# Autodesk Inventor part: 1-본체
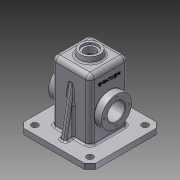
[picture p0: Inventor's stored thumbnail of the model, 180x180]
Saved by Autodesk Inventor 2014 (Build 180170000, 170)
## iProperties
Created: 2016-02
Part Number: 1-본체
Material: 알루미늄 6061
Document SubType Name: Modeling
Designer: G.C.Oh
Density: 2.71 g/cm^3
Appearance: 알루미늄 - 평지
Mass: 932.812 g
Surface Area: 1043.49 cm^2
Volume: 344.211 cm^3
Author: G.C.Oh
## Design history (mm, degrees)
sketch "스케치1"
  geometry: L1 (65, -65)-(-65, -65); L2 (-65, -65)-(-65, 65); L3 (-65, 65)-(65, 65); L4 (65, 65)-(65, -65); L5 (65, -65)-(-65, 65); L6 (-65, -65)-(65, 65); 1 further point
  constraints: 12 end point, 2 midpoint, 2 parallel, 1 horizontal, 1 perpendicular
  dimensions: "d0" = 130 distance of L2.end L3.end; "d1" = 130 distance of L1.end L2.end
extrude "돌출1" new body sketch "스케치1" distance "d2" = 10; taper "d3" = 0 deg
sketch "스케치2"
  geometry: L1 (-35, -35)-(35, -35); L2 (35, -35)-(35, 35); L3 (35, 35)-(-35, 35); L4 (-35, 35)-(-35, -35); L5 (-35, -35)-(35, 35); L6 (35, -35)-(-35, 35); 1 further point
  constraints: 12 end point, 2 midpoint, 2 parallel, 1 horizontal, 1 perpendicular
  dimensions: "d4" = 70 distance of L1.end L2.end; "d5" = 70 distance of L2.end L3.end
extrude "돌출2" join sketch "스케치2" distance "d6" = 110; taper "d7" = 0 deg
sketch "스케치3"
  geometry: L1 (0, 120)-(-20, 120); L2 (-20, 120)-(-18.237, 130); L3 (-18.237, 130)-(0, 130); L4 (0, 130)-(0, 120); L5 (-35, 10)-(-35, 120) reference; L6 (-35, 120)-(35, 120) reference; 1 further point
  constraints: 8 end point, 1 collinear, 1 horizontal, 1 parallel, 1 perpendicular, 1 vertical alignment
  dimensions: "d9" = 40 diameter of L1.end L4; "d10" = 10 deg angle of L5 L2; "d11" = 10 distance between parallel lines of L1 L3
revolve "회전1" sketch "스케치3" stored, may be unused: angle "d12" = 90 deg
fillet "모깎기1" dims "d13" = 8
sketch "스케치4"
  geometry: C1 r 27.5 at (0, 55); 1 further point
  constraints: 1 centre point, 1 vertical alignment
  dimensions: "d14" = 55 distance of point (0, 0) C1.centre; "d15" = 55 diameter of C1
extrude "돌출3" join sketch "스케치4" stored distance "d16" = 96; taper "d17" = 0 deg
sketch "스케치5"
  geometry: L1 (30, 0)-(-30, 0); L2 (-30, 0)-(-30, 115); L3 (-30, 115)-(30, 115); L4 (30, 115)-(30, 0); L5 (35, 10)-(35, 49.78) reference; L6 (-35, 49.78)-(-35, 10) reference; L7 (-27, 120)-(27, 120) reference; 1 further point
  constraints: 8 end point, 2 parallel, 1 horizontal, 1 midpoint, 1 perpendicular
  dimensions: "d18" = 5 distance between parallel lines of L5 L4; "d19" = 5 distance between parallel lines of L6 L2; "d20" = 5 distance between parallel lines of L7 L3
extrude "돌출4" cut sketch "스케치5" stored distance "d21" = 60; taper "d22" = 0 deg
fillet "모깎기2" dims "d23" = 8
hole "구멍1" diameter "d26" = 21; stored, may be unused: countersink angle "d30" = 90 deg, drill point angle "d32" = 118 deg; dims "d24" = 10, "d25" = 10, "d27" = 6, "d28" = 28, "d29" = 4, "d31" = 8
sketch "스케치6"
  geometry: L1 (-30, 82.5)-(-23, 75.5); L2 (-23, 75.5)-(-23, 55); L3 (-23, 55)-(-30, 55); L4 (-30, 55)-(-30, 82.5); L5 (-30, 115)-(-30, 0) reference; L6 (-35, 82.5)-(-48, 82.5) reference; 1 further point
  constraints: 8 end point, 2 perpendicular, 1 collinear, 1 point on line, 1 vertical
  dimensions: "d33" = 55 diameter of L1.start L3; "d34" = 7 distance between parallel lines of L4 L2; "d35" = 135 deg angle of L5 L1
revolve "회전2" sketch "스케치6" stored, may be unused: angle "d36" = 90 deg
sketch "스케치7"
  geometry: L1 (0, 0)-(-22.5, 0); C1 r 27.5 at (0, 0) reference; 1 further point
  constraints: 2 end point, 1 horizontal
  dimensions: "d37" = 22.5 distance of L1.start L1.end
hole "구멍2" sketch "스케치7" at (-22.5, 0) diameter "d38" = 3.242; stored, may be unused: countersink angle "d42" = 90 deg, drill point angle "d44" = 118 deg; dims "d39" = 8, "d40" = 28, "d41" = 4, "d43" = 10
hole "구멍3" diameter "d50" = 32; stored, may be unused: countersink angle "d54" = 90 deg, drill point angle "d56" = 118 deg; dims "d48" = 10, "d49" = 10, "d51" = 8, "d52" = 28, "d53" = 4, "d55" = 10
sketch "스케치8"
  geometry: L1 (50, 10)-(39.934, 67.084); L2 (-65, 10)-(65, 10) reference; L3 (65, 0)-(65, 10) reference; 1 further point
  constraints: 2 end point, 1 point on line
  dimensions: "d57" = 15 distance from line of L3 L1.start; "d58" = 10 deg angle of L3 L1
feature "리브1" sketch "스케치8" dims "d59" = 1, "d60" = 10, "d61" = 0, "d62" = 0, "d63" = 1, "d64" = 1
chamfer "모따기1" distance "d65" = 10; stored, may be unused: second distance "d66" = 2, angle "d67" = 45 deg
sketch "스케치9"
  geometry: L1 (50, -50)-(-50, -50); L2 (-50, -50)-(-50, 50); L3 (-50, 50)-(50, 50); L4 (50, 50)-(50, -50); L5 (50, -50)-(-50, 50); L6 (-50, -50)-(50, 50); 1 further point
  constraints: 12 end point, 2 midpoint, 2 parallel, 1 horizontal, 1 perpendicular
  dimensions: "d68" = 100 distance of L2.end L3.end; "d69" = 100 distance of L1.end L2.end
hole "구멍4" sketch "스케치9" at (-50, 50), (-50, -50), (50, -50), (50, 50) diameter "d70" = 12; stored, may be unused: countersink angle "d74" = 90 deg, drill point angle "d76" = 118 deg; dims "d71" = 8, "d72" = 28, "d73" = 4, "d75" = 10
fillet "모깎기3" dims "d77" = 0.5
sketch "스케치10"
  geometry: L1 (102, 62)-(0, 62) reference; L2 (-18, 45.237)-(-18, 8.763) reference; 2 further points
  constraints: 1 other
  dimensions: "d78" = 35 distance from line of L1 point (12, 27); "d79" = 30 distance from line of L2 point (12, 27)
feature "엠보싱1" sketch "스케치10" dims "d0" = 130, "d1" = 130, "d80" = 0.5, "d81" = 0
fillet "모깎기4" dims "d82" = 3
fillet "모깎기5" dims "d83" = 3
chamfer "모따기2" distance "d84" = 1; stored, may be unused: second distance "d85" = 2, angle "d86" = 45 deg
fillet "모깎기6" dims "d87" = 3
fillet "모깎기7" dims "d88" = 3
fillet "모깎기8" dims "d89" = 3
node "솔리드1"
pattern_circular "원형 패턴1" dims angle "d46" = 360 deg
mirror "대칭1"
mirror "대칭2"
